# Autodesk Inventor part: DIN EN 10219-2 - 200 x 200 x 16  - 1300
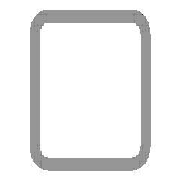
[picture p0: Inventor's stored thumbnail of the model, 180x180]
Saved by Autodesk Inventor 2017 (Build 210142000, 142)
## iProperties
Created: 2017-11
Part Number: DIN EN 10219-2 - 200 x 200 x 16  - 1300
Material: Steel, Mild
Description: Cold formed welded structural hollow sections of non-alloy and fine grain structural steel
Document SubType Name: Modeling
Standard: DIN
Designer: iusti
Standard Revision: 2006-07
Standards Organization: DIN
Language: en-US
Size Designation: 200 x 200 x 16
Categories: <MemberInstance><Categories><Category DisplayName="Structural Shapes" InternalName="089c4875-fa83-4c05-b084-43b9cc11f5ed" Mnemonic="GRDR"><CategoryParameter Dis
Stock Number: 200 x 200 x 16
Mass: 108961 g
Surface Area: 17564.1 cm^2
Volume: 13880.4 cm^3
Density: 7.85 g/cm^3
Appearance: Semi-Polished
_CCFamilyMember: 103
_CCFamilyDisplayName: DIN EN 10219-2 (Square Hollow Section - Cold Formed) - Cold formed welded structural hollow sections of non-alloy and fine grain structural steel
_FrameMemberDoc: Frame Member File
_Version: 15.0.0
_GetPNFromCC: 1
G_L: 1300.000 mm
G_W: 200.000 mm
G_H: 200.000 mm
+6716C19D-968C-41AC-94F2-3194A5FEB298+CUTDETAIL1: Cut
+49856AF1-55B6-4B33-98D5-46D5E76A574D+CUTDETAIL2: Cut
IsCustomPart: 1
Author: iusti
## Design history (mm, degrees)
node "Start plane"
node "End plane"
sketch "Sketch"
  geometry: L1 (-100, -52)-(-100, 52); L2 (-52, 100)-(52, 100); L3 (100, 52)-(100, -52); L4 (52, -100)-(-52, -100); L5 (-52, 84)-(52, 84); L6 (84, 52)-(84, -52); L7 (52, -84)-(-52, -84); L8 (-84, -52)-(-84, 52); L9 (0, 153.918)-(0, -153.918) reference; L10 (-153.918, 0)-(153.918, 0) reference; A1 r 48 centre (-52, -52) between (-100, -52) and (-52, -100); A2 r 48 centre (-52, 52) between (-52, 100) and (-100, 52); A3 r 48 centre (52, 52) between (100, 52) and (52, 100); A4 r 48 centre (52, -52) between (52, -100) and (100, -52); A5 r 32 centre (-52, 52) between (-52, 84) and (-84, 52); A6 r 32 centre (52, 52) between (84, 52) and (52, 84); A7 r 32 centre (52, -52) between (52, -84) and (84, -52); A8 r 32 centre (-52, -52) between (-84, -52) and (-52, -84)
  constraints: 16 end point, 16 point on circle, 8 centre point, 8 tangent, 4 parallel, 3 equal radius, 2 perpendicular, 7 other
  dimensions: "d7" = 48 radius of A1 (= G_IR); "d10" = 200 distance between parallel lines of L2 L4 (= G_H); "d11" = 200 distance between parallel lines of L1 L3 (= G_W); "d12" = 16 distance between parallel lines of L3 L6 (= G_T); "d15" = 100 distance between parallel lines of L2 L10 (= 0.5 x d10); "d16" = 100 distance between parallel lines of L9 L3 (= 0.5 x d11)
extrude "Body" new body sketch "Sketch" stored distance "d3" = 1300 (= G_L); taper "d4" = 0 deg
node "Driven Length"
  sketch "Sketch3"
    geometry: L1 (0, 0)-(10, 0) reference
    constraints: 2 end point, 1 horizontal
  workplane "Work Plane3"
  sketch "Sketch4"
    geometry: L1 (-2, 100)-(12, 100) reference; L2 (-2, 1400)-(12, 1400) reference
    dimensions: "d18" = 1300 distance between parallel lines of L1 L2 (derived)
workplane "Work Plane4"
split "Split1"
workplane "Work Plane5"
split "Split2"
body "Solid1"
other parameters: "G_W" = 200 [user parameter; used in 1 equation term], "G_H" = 200 [user parameter; used in 1 equation term], "G_T" = 16 [user parameter; used in 1 equation term], "G_IR" = 48 [user parameter; used in 1 equation term], "G_L" = 1300 (= d18) [user parameter; used in 1 equation term], "d17" = 90 deg
